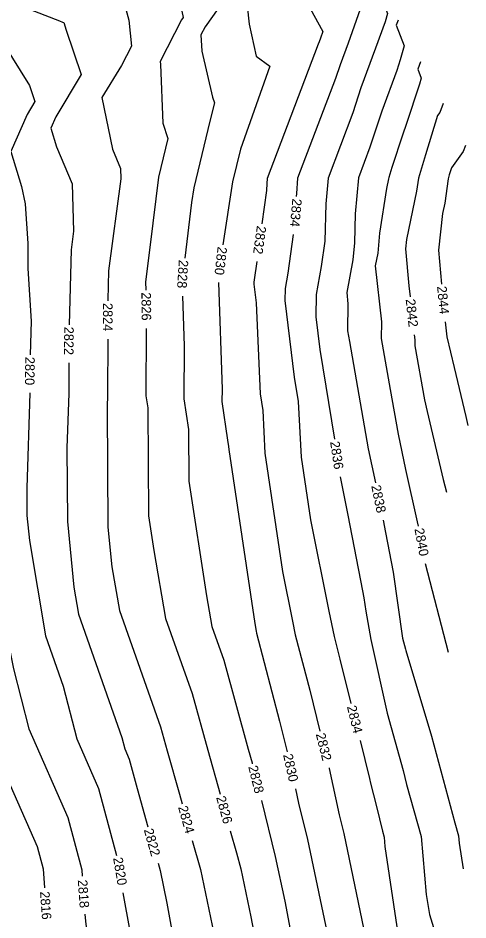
# Model space of a CAD drawing. Extents: x 1326424 to 1329294, y 1001359 to 1003823.
# Drawn here: x 1328442.1 to 1328536.7, y 1002879.4 to 1003069 of the extents above; entities that cross this region are included whole.
import ezdxf

# ---------------------------------------------------------------- set-up
doc = ezdxf.new("R2010")
doc.units = 0
doc.layers.add('Prop Rem of Exist Asph Pvmt', color=7, linetype='Continuous')
doc.layers.add('Scratch_Level_3', color=7, linetype='Continuous')

msp = doc.modelspace()

# ---------------------------------------------------------------- linework, layer by layer
at = {"layer": 'Prop Rem of Exist Asph Pvmt'}
for points in [[(1328408.93, 1003070.24), (1328414.29, 1003069.49), (1328420.74, 1003069.38), (1328426.4, 1003068.39), (1328426.81, 1003068.35), (1328428.23, 1003068.16), (1328434.26, 1003065.58), (1328438.93, 1003063.75), (1328444.47, 1003054.84), (1328445.63, 1003051.44), (1328444.03, 1003048.74), (1328440.53, 1003040.95), (1328442.81, 1003033.58), (1328443.58, 1003029.94), (1328444.11, 1003021.64), (1328444.15, 1003016.37), (1328444.82, 1003005.3), (1328444.64, 1002998.21)], [(1328526.76, 1003059.77), (1328526.16, 1003058.23), (1328526.9, 1003056.34), (1328526.52, 1003055.07), (1328523.76, 1003046.66), (1328523.01, 1003044.61), (1328520.7, 1003037.57), (1328520.05, 1003035.48), (1328520.01, 1003035.19), (1328519.6, 1003033.21), (1328518.13, 1003023.78), (1328517.75, 1003019.61), (1328517.24, 1003016.89), (1328518.52, 1003005.14), (1328518.46, 1003001.66), (1328520.39, 1002990.9), (1328522.04, 1002981.52), (1328523.59, 1002974.12), (1328526.05, 1002963.11), (1328526.27, 1002962.19)], [(1328444.54, 1002990.21), (1328444.54, 1002990.15), (1328443.92, 1002970.29), (1328443.96, 1002964.45), (1328444.48, 1002959.22), (1328447.87, 1002939.16), (1328451.59, 1002928.57), (1328454.42, 1002917.51), (1328459.03, 1002907.11), (1328462.77, 1002892.98)], [(1328527.74, 1002954.33), (1328532.53, 1002935.75)], [(1328464.1, 1002885.12), (1328468.24, 1002862.49), (1328468.4, 1002861.72), (1328469.35, 1002858.05), (1328474.36, 1002838.04), (1328475.26, 1002832.79), (1328479.29, 1002813.47), (1328481.11, 1002800.89), (1328482.17, 1002787.56), (1328482.16, 1002786.92)]]:
    msp.add_lwpolyline(points, dxfattribs=at)
at = {"layer": 'Scratch_Level_3'}
for points in [[(1328478.9, 1003107.82), (1328487.1, 1003105.83), (1328500.48, 1003102.7), (1328503.18, 1003100.07), (1328511.09, 1003086.67), (1328512.1, 1003085.12), (1328512.07, 1003084.61), (1328511.75, 1003084.15), (1328513.04, 1003074.67), (1328514.48, 1003072.03), (1328511.51, 1003063.73), (1328509.81, 1003059.14), (1328508.87, 1003056.28), (1328500.9, 1003035.32), (1328500.63, 1003032.11), (1328500.61, 1003031.48)], [(1328471.97, 1003102.02), (1328484.09, 1003098.54), (1328488, 1003097.59), (1328491.53, 1003096.77), (1328494.42, 1003093.96), (1328502.58, 1003083.62), (1328503.42, 1003082.11), (1328503.4, 1003081.88), (1328500.63, 1003077.78), (1328500.89, 1003075.9), (1328506.21, 1003066.18), (1328505.7, 1003064.76), (1328505.41, 1003063.98), (1328505.25, 1003063.49), (1328494.52, 1003035.26), (1328494.43, 1003034.25), (1328494.38, 1003032.77), (1328493.4, 1003025.73)], [(1328463.16, 1003096.28), (1328468.14, 1003095.62), (1328481.18, 1003091.88), (1328485.61, 1003090.58), (1328492.08, 1003081.33), (1328494.83, 1003078.12), (1328494.14, 1003077.14), (1328492.97, 1003075.31), (1328490.28, 1003071.54), (1328490.69, 1003067.69), (1328492.17, 1003060.97), (1328495.07, 1003058.87), (1328488.86, 1003041.45), (1328487.19, 1003034.56), (1328485.16, 1003021.35)], [(1328452.25, 1003091.09), (1328454.52, 1003090.79), (1328461.82, 1003089.37), (1328463.19, 1003089.13), (1328465.89, 1003088.77), (1328470.04, 1003087.58), (1328481.37, 1003084.25), (1328485, 1003079.06), (1328486.68, 1003074.5), (1328486.43, 1003074.11), (1328484.2, 1003070.98), (1328481.41, 1003067.16), (1328480.55, 1003065.48), (1328480.71, 1003062.01), (1328483, 1003052.38), (1328483.39, 1003051.2), (1328482.46, 1003047.32), (1328479.06, 1003033.3), (1328478.58, 1003030.22), (1328477.17, 1003018.54)], [(1328444.25, 1003085.52), (1328450.71, 1003084.66), (1328459.48, 1003082.96), (1328462.02, 1003081.9), (1328467.24, 1003080.12), (1328475.14, 1003077.91), (1328476.56, 1003070.46), (1328476.85, 1003069.13), (1328476.5, 1003068.65), (1328472, 1003059.88), (1328472.03, 1003059.21), (1328472.53, 1003046.9), (1328473.58, 1003043.69), (1328471.63, 1003035.54), (1328469.87, 1003021.32), (1328468.92, 1003013.53), (1328468.98, 1003011.78)], [(1328431.08, 1003080.59), (1328431.78, 1003080.51), (1328432.12, 1003080.51), (1328433.1, 1003080.37), (1328446.91, 1003078.53), (1328449.43, 1003078.04), (1328456.73, 1003075.02), (1328464.35, 1003072.41), (1328465.4, 1003068.57), (1328465.98, 1003063.11), (1328463.86, 1003059.02), (1328459.68, 1003052.29), (1328461.93, 1003041.44), (1328463.66, 1003037.37), (1328463.73, 1003035.22), (1328461.14, 1003015.84), (1328460.98, 1003009.69), (1328460.98, 1003009.54)], [(1328517.3, 1003077.3), (1328517.12, 1003076.83), (1328519.79, 1003069.94), (1328519.28, 1003068.18), (1328517.31, 1003062.69), (1328514.21, 1003054.3), (1328512.49, 1003049.06), (1328507.29, 1003035.38), (1328506.83, 1003029.98), (1328506.59, 1003022.12), (1328505.85, 1003016.78), (1328504.8, 1003010.88), (1328504.72, 1003006.21), (1328505.57, 1002999.35), (1328508.67, 1002980.51)], [(1328419.55, 1003075.51), (1328423.73, 1003074.93), (1328425.42, 1003074.9), (1328426.9, 1003074.64), (1328429.61, 1003074.39), (1328438.96, 1003073.11), (1328441.22, 1003072.15), (1328450.82, 1003068.39), (1328451.43, 1003068.13), (1328451.74, 1003068.03), (1328452.17, 1003066.47), (1328455.35, 1003057.14), (1328450.03, 1003048.22), (1328448.96, 1003045.84), (1328450.18, 1003041.9), (1328453.47, 1003034.18), (1328453.76, 1003024.18), (1328453.24, 1003020.31), (1328452.82, 1003004.53)], [(1328522.03, 1003068.54), (1328521.64, 1003067.53), (1328523.34, 1003063.14), (1328522.48, 1003060.19), (1328521.75, 1003057.97), (1328518.61, 1003049.45), (1328516.12, 1003041.85), (1328513.68, 1003035.44), (1328513.03, 1003027.85), (1328512.85, 1003021.78), (1328512.52, 1003018.18), (1328511.23, 1003011.35), (1328511.49, 1003008.93), (1328511.39, 1003003.25), (1328511.79, 1003001.03), (1328515.74, 1002978.48), (1328517.25, 1002971.3)], [(1328531.49, 1003051.01), (1328530.78, 1003049.18), (1328530.3, 1003048.52), (1328527.81, 1003040.24), (1328526.29, 1003035.34), (1328525.93, 1003032.65), (1328523.79, 1003022.43), (1328523.56, 1003020.48), (1328524.31, 1003012.71), (1328524.56, 1003010.39)], [(1328536.22, 1003042.24), (1328535.71, 1003040.93), (1328533.24, 1003037.55), (1328532.8, 1003036.08), (1328532.53, 1003035.2), (1328531.84, 1003030.1), (1328531.39, 1003027.95), (1328530.5, 1003020.22), (1328531.19, 1003013.09)], [(1328499.94, 1003023.52), (1328498.8, 1003015.39), (1328498.24, 1003012.19), (1328498.19, 1003009.65), (1328500.2, 1002993.53), (1328501.03, 1002988.43), (1328501.65, 1002976.73), (1328503.61, 1002963.54), (1328507.48, 1002944.36), (1328508.55, 1002939.05), (1328509.8, 1002934.23), (1328512.11, 1002924.93)], [(1328492.29, 1003017.81), (1328491.76, 1003014), (1328491.67, 1003013.49), (1328491.66, 1003013.1), (1328492.15, 1003009.13), (1328492.98, 1002990), (1328493.56, 1002986.49), (1328494.03, 1002977.52), (1328497.74, 1002952.65), (1328499.83, 1002942.25), (1328500.41, 1002939.38), (1328503.45, 1002927.72), (1328505.57, 1002919.15)], [(1328484.23, 1003013.41), (1328485, 1002990.98), (1328484.98, 1002988.4), (1328486.15, 1002980.29), (1328486.38, 1002978.92), (1328486.41, 1002978.3), (1328491.86, 1002941.76), (1328492.18, 1002940.15), (1328492.27, 1002939.7), (1328497.09, 1002921.21), (1328498.69, 1002914.79)], [(1328476.68, 1003010.58), (1328477.03, 1003000.08), (1328476.98, 1002988.99), (1328477.91, 1002982.54), (1328477.98, 1002971.65), (1328481.71, 1002947.57), (1328482.84, 1002941.13), (1328485.36, 1002934.03), (1328490.52, 1002915.31), (1328491.32, 1002912.44), (1328491.36, 1002912.28)], [(1328531.96, 1003005.13), (1328532.26, 1003001.97), (1328533.81, 1002995.59), (1328536.26, 1002985.25), (1328536.73, 1002983.34)], [(1328469.05, 1003003.78), (1328468.98, 1002989.59), (1328469.35, 1002987.05), (1328469.49, 1002964.4), (1328470.61, 1002957.13), (1328473.13, 1002942.82), (1328478.72, 1002927.02), (1328481.99, 1002915.15), (1328484.58, 1002905.87)], [(1328460.95, 1003001.54), (1328460.91, 1002990), (1328460.82, 1002987.03), (1328460.98, 1002961.97), (1328461.8, 1002953.65), (1328463.41, 1002944.5), (1328472.08, 1002920.01), (1328473.46, 1002914.99), (1328476.01, 1002905.85), (1328476.58, 1002903.82)], [(1328525.44, 1003002.44), (1328525.55, 1003001.36), (1328525.53, 1003000.08), (1328527.56, 1002988.79), (1328528.15, 1002986.34), (1328531.54, 1002972.01), (1328532.2, 1002969.36)], [(1328452.75, 1002996.53), (1328452.73, 1002990.07), (1328452.37, 1002978.66), (1328452.47, 1002963.21), (1328453.83, 1002949.39), (1328454.79, 1002943.72), (1328463.92, 1002917.76), (1328464.51, 1002915.43), (1328465.48, 1002913.24), (1328467.11, 1002907.09), (1328469.37, 1002899.05)], [(1328435.87, 1002985.6), (1328435.3, 1002969.43), (1328435.36, 1002964.65), (1328439.72, 1002939.39), (1328440.29, 1002936.42), (1328441.09, 1002932.21), (1328444.33, 1002919.59), (1328452.57, 1002900.99), (1328455.48, 1002890.01), (1328455.58, 1002888.65)], [(1328426.5, 1002982.84), (1328426.4, 1002980.23), (1328426.62, 1002963.25), (1328428.86, 1002950.27), (1328431.26, 1002937.74), (1328434.19, 1002922.49), (1328434.62, 1002920.74), (1328436.24, 1002917.16), (1328446.12, 1002894.86), (1328447.36, 1002890.19), (1328447.65, 1002886.21)], [(1328509.86, 1002972.61), (1328511.49, 1002964.51), (1328514.53, 1002948.61), (1328514.82, 1002947.15), (1328515.22, 1002944.32), (1328516.31, 1002938.4), (1328519.73, 1002922.91), (1328523.1, 1002910.89), (1328523.8, 1002907.93), (1328526.9, 1002896.98), (1328527.96, 1002884.8), (1328528.66, 1002880.57), (1328530.41, 1002874.94)], [(1328518.87, 1002963.46), (1328519.37, 1002960.87), (1328521, 1002952.52), (1328522.97, 1002938.65), (1328523.56, 1002936.39), (1328523.65, 1002936.05), (1328529.04, 1002918.08), (1328533.95, 1002899.85), (1328534.73, 1002897.1), (1328534.86, 1002895.59), (1328535.75, 1002890.22)], [(1328514.04, 1002917.17), (1328516.02, 1002909.21), (1328516.23, 1002908.22), (1328517.49, 1002903.29), (1328518.72, 1002898.11), (1328519.07, 1002896.87), (1328519.25, 1002894.86), (1328521.97, 1002876.6), (1328524.94, 1002868.96), (1328525.46, 1002867.31), (1328526.1, 1002864.11), (1328527.31, 1002854.7), (1328528.9, 1002846.82), (1328530.29, 1002837.72), (1328530.72, 1002831.74), (1328530.92, 1002824.31), (1328531.03, 1002823.24), (1328531.07, 1002820.19), (1328531.06, 1002819.06)], [(1328507.5, 1002911.39), (1328507.52, 1002911.31), (1328509.64, 1002901.54), (1328510.65, 1002897.59), (1328515.49, 1002873.98), (1328516.22, 1002869.09), (1328517.01, 1002867.05), (1328517.81, 1002863.42), (1328518.33, 1002859.39), (1328522.69, 1002837.77), (1328522.77, 1002837.24), (1328522.79, 1002836.71), (1328523.46, 1002830.1), (1328523.72, 1002813.04)], [(1328500.42, 1002906.98), (1328501.07, 1002903.98), (1328502.96, 1002896.35), (1328507.69, 1002874.04), (1328509.1, 1002866.58), (1328509.91, 1002862.18), (1328510.73, 1002858.46), (1328514.98, 1002841.42), (1328515.83, 1002837.61), (1328515.9, 1002836.96), (1328515.94, 1002833.89), (1328516.54, 1002809.45), (1328516.6, 1002808.7)], [(1328493.29, 1002904.52), (1328496.19, 1002892.81), (1328498.19, 1002883.39), (1328501.51, 1002865.85), (1328501.98, 1002863.27), (1328504.36, 1002852.5), (1328507.86, 1002838.46), (1328508.88, 1002831.77), (1328509.39, 1002811.12), (1328509.8, 1002806.23)], [(1328486.72, 1002898.17), (1328488.01, 1002893.54), (1328488.96, 1002890.18), (1328491.08, 1002880.09), (1328493.91, 1002865.11), (1328494.05, 1002864.37), (1328497.99, 1002846.54), (1328499.78, 1002839.37), (1328501.93, 1002825.25), (1328502.23, 1002812.78), (1328503.32, 1002799.83)], [(1328478.74, 1002896.12), (1328480.45, 1002890.02), (1328484.33, 1002871.59), (1328485.66, 1002864.25), (1328491.3, 1002842.02), (1328491.62, 1002840.59), (1328491.69, 1002840.28), (1328494.97, 1002818.73), (1328495.08, 1002814.45), (1328496.46, 1002797.94)], [(1328471.54, 1002891.35), (1328471.95, 1002889.86), (1328473.4, 1002882.99), (1328476.97, 1002863.29), (1328479.93, 1002851.62), (1328483.04, 1002839.21), (1328486.15, 1002820.96), (1328487.45, 1002814.73), (1328488.04, 1002810.67), (1328489.42, 1002793.12)], [(1328456.16, 1002880.67), (1328456.32, 1002878.49), (1328459.11, 1002863.23), (1328461.06, 1002853.58), (1328465.27, 1002837.37), (1328470.93, 1002812.9), (1328471.08, 1002812.28), (1328471.1, 1002812.15), (1328471.18, 1002811.63), (1328471.68, 1002808.46), (1328474.19, 1002791.12), (1328474.42, 1002788.19), (1328474.35, 1002782.56)]]:
    msp.add_lwpolyline(points, dxfattribs=at)

# ---------------------------------------------------------------- texts
at = {"layer": 'Prop Rem of Exist Asph Pvmt'}
for s, rotation, p in [('2820', 269.3197, (1328443.6, 1002997.8)), ('2840', 280.6255, (1328525.46, 1002961.62)), ('2820', 279.6012, (1328462.07, 1002892.46))]:
    msp.add_text(s, height=2, rotation=rotation, dxfattribs=at).set_placement(p)
at = {"layer": 'Scratch_Level_3'}
for s, rotation, p in [('2834', 265.192, (1328499.79, 1003031.1)), ('2832', 262.0308, (1328492.35, 1003025.43)), ('2830', 263.3459, (1328484.09, 1003021.03)), ('2828', 266.4522, (1328475.91, 1003018.21)), ('2844', 275.5181, (1328530.23, 1003012.58)), ('2826', 270.4509, (1328468.04, 1003011.36)), ('2824', 269.8047, (1328459.98, 1003009.12)), ('2842', 276.2484, (1328523.62, 1003009.87)), ('2822', 269.4656, (1328451.8, 1003004.13)), ('2836', 278.5836, (1328507.72, 1002979.92)), ('2838', 281.7158, (1328516.37, 1002970.66)), ('2834', 283.9549, (1328511.25, 1002924.26)), ('2832', 283.9549, (1328504.71, 1002918.48)), ('2830', 282.5225, (1328497.83, 1002914.14)), ('2828', 283.9283, (1328490.49, 1002911.64)), ('2826', 285.5667, (1328483.73, 1002905.2)), ('2824', 285.692, (1328475.73, 1002903.15)), ('2822', 285.692, (1328468.52, 1002898.38)), ('2818', 274.168, (1328454.64, 1002887.83)), ('2816', 274.168, (1328446.7, 1002885.39))]:
    msp.add_text(s, height=2, rotation=rotation, dxfattribs=at).set_placement(p)

doc.saveas('drawing.dxf')
